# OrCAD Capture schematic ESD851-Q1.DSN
size A; title: ESD851-Q1 36V Bidirectional ESD Protection Diode in SOD-323; rev: 1.0; note: Datasheet: SLVSIB5
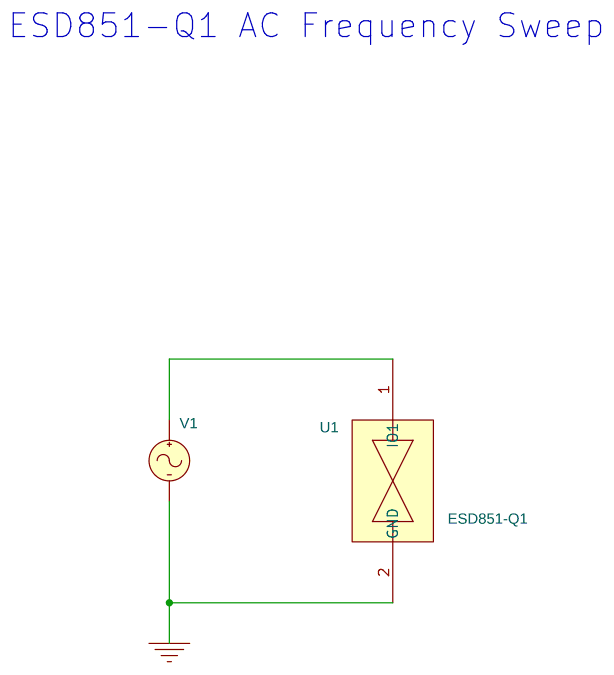
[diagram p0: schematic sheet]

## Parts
U1  ESD851-Q1
V1  VAC

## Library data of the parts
U1 = ESD851-Q1
V1 = VAC

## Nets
0: U1.2(GND) V1.2(-)
N02931: U1.1(IO1) V1.1(+)

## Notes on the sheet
- ESD851-Q1 AC Frequency Sweep
